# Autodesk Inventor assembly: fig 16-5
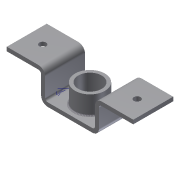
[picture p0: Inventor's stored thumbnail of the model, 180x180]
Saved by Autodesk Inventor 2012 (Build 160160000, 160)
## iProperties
Created: 2004-07
Part Number: fig 16-5
Document SubType Name: Weldment
Designer: CADCIM Technologies
Manufacturer: Standard
Standards Organization: Custom
Author: CADCIM Technologies
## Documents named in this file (3)
- C:\Users\CadCim\Documents\SAILESH\inventor-2011-fact-prt\c16-inv-2011-prt\c16_inv_2012_prt\fig 16-5\fig 16-5.iam
- C:\Users\CadCim\Documents\SAILESH\inventor-2011-fact-prt\c16-inv-2011-prt\fig-16-5\Bracket.ipt
- C:\Users\CadCim\Documents\SAILESH\inventor-2011-fact-prt\c16-inv-2011-prt\fig-16-5\cylinder.ipt
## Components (2 placed, 2 different names)
1. Bracket:1 — Insert:1
2. cylinder:1 — Insert:1
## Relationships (1: Insert 1)
- Insert:1: Bracket:1 ↔ cylinder:1
